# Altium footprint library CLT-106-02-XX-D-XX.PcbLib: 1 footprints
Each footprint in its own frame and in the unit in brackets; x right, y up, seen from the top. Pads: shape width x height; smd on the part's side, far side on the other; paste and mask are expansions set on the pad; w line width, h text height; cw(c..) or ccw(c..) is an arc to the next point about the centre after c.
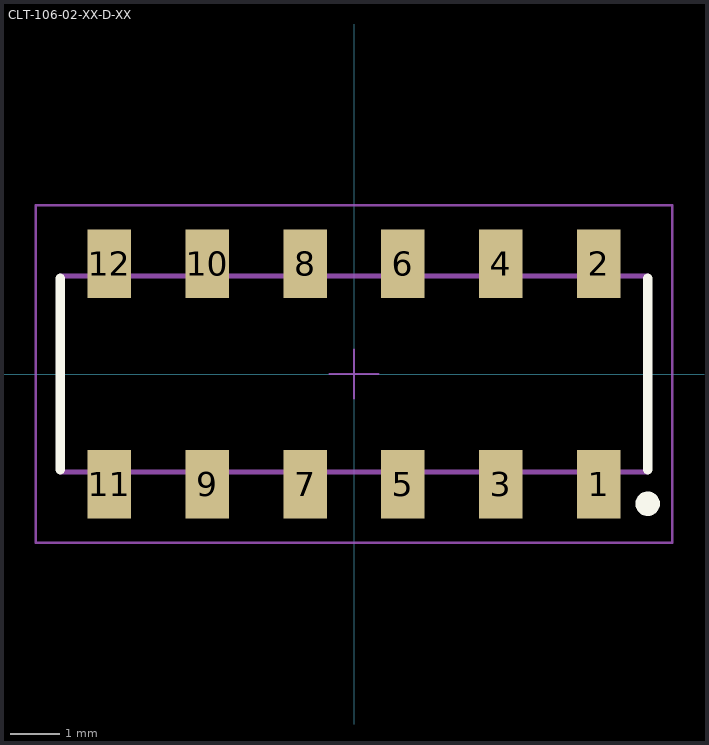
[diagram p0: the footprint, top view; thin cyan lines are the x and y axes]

## CLT-106-02-XX-D-XX [mm] "2.00mm pitch, 12 pin, header; low profile"
height 2.13
pads (12):
  rect 0.89x1.4 smd mask+0: 1(5,-2.25) 2(5,2.25) 3(3,-2.25) 4(3,2.25) 5(1,-2.25) 6(1,2.25) 7(-1,-2.25) 8(-1,2.25) 9(-3,-2.25) 10(-3,2.25) 11(-5,-2.25) 12(-5,2.25)
Top Overlay:
  circle w0.25: c6,-2.65 r0.125
  lines w0.2: -6,-1.95 -6,1.95 ; 6,-1.95 6,1.95
Mechanical 12:
  lines w0.001: -6,-2 6,-2 6,2 -6,2 -6,-2
Mechanical 13:
  lines w0.1: -6,-2 6,-2 6,2 -6,2 -6,-2
  text ".Designator" at 0.254,0.254 h1.52
Mechanical 15:
  lines w0.05: -0.5,0 0.5,0 ; 0,-0.5 0,0.5 ; -6.5,-3.45 6.5,-3.45 6.5,3.45 -6.5,3.45 -6.5,-3.45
